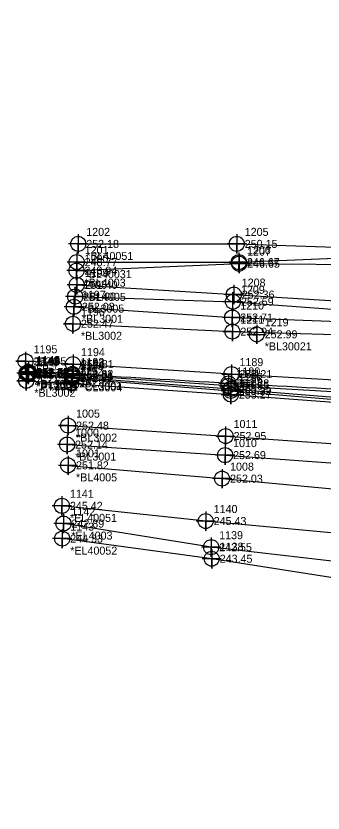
# Model space of a CAD drawing. Extents: x 2130962 to 2131465, y 643052 to 644206.
# Drawn here: x 2130981.3 to 2131077.2, y 643057.4 to 643306.2 of the extents above; entities that cross this region are included whole.
import ezdxf

# ---------------------------------------------------------------- set-up
doc = ezdxf.new("R2010")
doc.units = 0
for name, color, linetype in [('Exist DTM Breakline', 7, 'Continuous'), ('Exist DTM Breakline Cogo Comment', 7, 'Continuous'), ('Exist DTM Breakline Cogo Elevation', 7, 'Continuous'), ('Exist DTM Breakline Cogo Number', 7, 'Continuous'), ('Exist DTM Breakline Cogo Point CELL', 7, 'Continuous'), ('Exist DTM Drainline', 7, 'Continuous'), ('Exist DTM Drainline Cogo Comment', 7, 'Continuous'), ('Exist DTM Drainline Cogo Elevation', 7, 'Continuous'), ('Exist DTM Drainline Cogo Number', 7, 'Continuous'), ('Exist DTM Drainline Cogo Point CELL', 7, 'Continuous'), ('Exist Roads Curbs', 7, 'Continuous'), ('Exist Roads Curbs Cogo Comment', 7, 'Continuous'), ('Exist Roads Curbs Cogo Elevation', 7, 'Continuous'), ('Exist Roads Curbs Cogo Number', 7, 'Continuous'), ('Exist Roads Curbs Cogo Point CELL', 7, 'Continuous'), ('Exist Roads EOP', 7, 'Continuous'), ('Exist Roads EOP Cogo Comment', 7, 'Continuous'), ('Exist Roads EOP Cogo Elevation', 7, 'Continuous'), ('Exist Roads EOP Cogo Number', 7, 'Continuous'), ('Exist Roads EOP Cogo Point CELL', 7, 'Continuous'), ('Exist Roads EOT', 7, 'Continuous'), ('Exist Roads EOT Cogo Comment', 7, 'Continuous'), ('Exist Roads EOT Cogo Elevation', 7, 'Continuous'), ('Exist Roads EOT Cogo Number', 7, 'Continuous'), ('Exist Roads EOT Cogo Point CELL', 7, 'Continuous'), ('Exist Roads Soil', 7, 'Continuous'), ('Exist Roads Soil Cogo Comment', 7, 'Continuous'), ('Exist Roads Soil Cogo Elevation', 7, 'Continuous'), ('Exist Roads Soil Cogo Number', 7, 'Continuous'), ('Exist Roads Soil Cogo Point CELL', 7, 'Continuous')]:
    doc.layers.add(name, color=color, linetype=linetype)

msp = doc.modelspace()

# ---------------------------------------------------------------- linework, layer by layer
at = {"layer": 'Exist DTM Breakline'}
for points in [[(2131000.7408, 643235.0731), (2131050.2503, 643235.0771), (2131099.3971, 643233.3967), (2131102.4734, 643233.467), (2131117.9784, 643240.6457), (2131141.4902, 643260.2289), (2131148.9668, 643267.309), (2131161.3925, 643274.3195), (2131169.1458, 643283.2692), (2131172.0772, 643292.493), (2131174.434, 643316.7319), (2131174.0607, 643347.0813), (2131174.2633, 643367.3367), (2131180.4607, 643413.966), (2131183.0424, 643464.7744), (2131179.7562, 643510.5479), (2131157.5016, 643561.2065), (2131139.0887, 643604.6918), (2131124.996, 643650.6897)], [(2131000.2707, 643222.2884), (2131049.3172, 643219.2511), (2131099.5024, 643216.1866), (2131123.0232, 643217.8518), (2131146.7721, 643223.5416), (2131166.8509, 643229.4959), (2131199.4918, 643255.6512), (2131208.4065, 643272.9132), (2131217.3052, 643317.6851), (2131214.0619, 643367.4973), (2131211.0353, 643416.1836)], [(2130997.5489, 643165.941), (2131045.6664, 643161.7962), (2131094.7686, 643157.2786), (2131146.0902, 643153.1147), (2131194.5413, 643146.0346), (2131212.7846, 643137.5737), (2131227.5943, 643121.2545), (2131235.8712, 643098.3644), (2131243.3589, 643075.7514)], [(2131203.7387, 643060.6768), (2131200.323, 643080.6622), (2131194.2334, 643094.4284), (2131190.0903, 643104.0511), (2131182.9576, 643105.8495), (2131138.023, 643121.5465), (2131094.1742, 643143.5026), (2131040.5455, 643148.5531), (2130995.6405, 643153.3049)], [(2131190.282, 643057.3997), (2131185.0957, 643076.1853), (2131183.224, 643089.154), (2131178.6092, 643094.5527), (2131136.9713, 643111.7747), (2131091.5821, 643129.064), (2131042.4244, 643136.794), (2130995.734, 643143.071)]]:
    msp.add_lwpolyline(points, dxfattribs=at)
at = {"layer": 'Exist DTM Breakline Cogo Point CELL'}
for points in [[(2131000.7408, 643238.0731), (2131000.7408, 643232.0731), (2131000.7408, 643235.0731), (2131003.7408, 643235.0731), (2130997.7408, 643235.0731)], [(2131050.2503, 643238.0771), (2131050.2503, 643232.0771), (2131050.2503, 643235.0771), (2131053.2503, 643235.0771), (2131047.2503, 643235.0771)], [(2131000.2707, 643225.2884), (2131000.2707, 643219.2884), (2131000.2707, 643222.2884), (2131003.2707, 643222.2884), (2130997.2707, 643222.2884)], [(2131049.3172, 643222.2511), (2131049.3172, 643216.2511), (2131049.3172, 643219.2511), (2131052.3172, 643219.2511), (2131046.3172, 643219.2511)], [(2130997.5489, 643168.941), (2130997.5489, 643162.941), (2130997.5489, 643165.941), (2131000.5489, 643165.941), (2130994.5489, 643165.941)], [(2131045.6664, 643164.7962), (2131045.6664, 643158.7962), (2131045.6664, 643161.7962), (2131048.6664, 643161.7962), (2131042.6664, 643161.7962)], [(2130995.6405, 643156.3049), (2130995.6405, 643150.3049), (2130995.6405, 643153.3049), (2130998.6405, 643153.3049), (2130992.6405, 643153.3049)], [(2131040.5455, 643151.5531), (2131040.5455, 643145.5531), (2131040.5455, 643148.5531), (2131043.5455, 643148.5531), (2131037.5455, 643148.5531)], [(2130995.734, 643146.071), (2130995.734, 643140.071), (2130995.734, 643143.071), (2130998.734, 643143.071), (2130992.734, 643143.071)], [(2131042.4244, 643139.794), (2131042.4244, 643133.794), (2131042.4244, 643136.794), (2131045.4244, 643136.794), (2131039.4244, 643136.794)]]:
    msp.add_lwpolyline(points, dxfattribs=at)
for centre in [(2131000.7408, 643235.0731), (2131050.2503, 643235.0771), (2131000.2707, 643222.2884), (2131049.3172, 643219.2511), (2130997.5489, 643165.941), (2131045.6664, 643161.7962), (2130995.6405, 643153.3049), (2131040.5455, 643148.5531), (2130995.734, 643143.071), (2131042.4244, 643136.794)]:
    msp.add_circle(centre, 2.344, dxfattribs=at)
at = {"layer": 'Exist DTM Drainline'}
for points in [[(2131000.2029, 643226.7228), (2131050.9884, 643228.9032), (2131099.0297, 643228.5605), (2131120.2968, 643239.3591), (2131144.9156, 643253.3469), (2131146.4739, 643252.3674), (2131154.3188, 643256.8046), (2131168.9618, 643265.5132), (2131176.6257, 643272.964), (2131179.8144, 643285.303), (2131183.3842, 643315.022), (2131190.1471, 643365.8731), (2131190.1489, 643413.686), (2131192.3886, 643466.4632), (2131188.8083, 643512.615), (2131184.0059, 643563.7066), (2131175.3, 643610.7482), (2131168.3784, 643658.7431), (2131156.7476, 643707.4708), (2131144.9036, 643754.0458), (2131132.9438, 643802.544), (2131118.0831, 643847.9475), (2131104.0084, 643896.8663), (2131096.3866, 643919.4077)], [(2131000.2521, 643229.3945), (2131050.9247, 643229.3918), (2131098.5522, 643231.3283), (2131118.2949, 643238.5741)], [(2131198.1997, 643059.006), (2131193.6429, 643078.1873), (2131189.8038, 643092.9639), (2131187.1852, 643097.4954), (2131182.6436, 643103.2956), (2131182.1533, 643099.9067), (2131137.3651, 643115.851), (2131092.5788, 643134.5516), (2131042.2635, 643140.3935), (2130996.1192, 643147.7639)]]:
    msp.add_lwpolyline(points, dxfattribs=at)
at = {"layer": 'Exist DTM Drainline Cogo Point CELL'}
for points in [[(2131000.2521, 643232.3945), (2131000.2521, 643226.3945), (2131000.2521, 643229.3945), (2131003.2521, 643229.3945), (2130997.2521, 643229.3945)], [(2131050.9247, 643232.3918), (2131050.9247, 643226.3918), (2131050.9247, 643229.3918), (2131053.9247, 643229.3918), (2131047.9247, 643229.3918)], [(2131050.9884, 643231.9032), (2131050.9884, 643225.9032), (2131050.9884, 643228.9032), (2131053.9884, 643228.9032), (2131047.9884, 643228.9032)], [(2131000.2029, 643229.7228), (2131000.2029, 643223.7228), (2131000.2029, 643226.7228), (2131003.2029, 643226.7228), (2130997.2029, 643226.7228)], [(2130996.1192, 643150.7639), (2130996.1192, 643144.7639), (2130996.1192, 643147.7639), (2130999.1192, 643147.7639), (2130993.1192, 643147.7639)], [(2131042.2635, 643143.3935), (2131042.2635, 643137.3935), (2131042.2635, 643140.3935), (2131045.2635, 643140.3935), (2131039.2635, 643140.3935)]]:
    msp.add_lwpolyline(points, dxfattribs=at)
for centre in [(2131000.2521, 643229.3945), (2131050.9247, 643229.3918), (2131050.9884, 643228.9032), (2131000.2029, 643226.7228), (2130996.1192, 643147.7639), (2131042.2635, 643140.3935)]:
    msp.add_circle(centre, 2.344, dxfattribs=at)
at = {"layer": 'Exist Roads Curbs'}
for points in [[(2131198.0624, 643180.7236), (2131148.4553, 643184.4513), (2131096.3634, 643187.9153), (2131047.6348, 643190.8052), (2130998.9825, 643194.049), (2130985.1601, 643194.9243)], [(2130985.2008, 643194.5895), (2130998.8721, 643193.5705), (2131048.4066, 643189.8131), (2131096.2876, 643185.9927), (2131148.0156, 643182.2174), (2131198.038, 643178.5389), (2131226.4879, 643176.4123)]]:
    msp.add_lwpolyline(points, dxfattribs=at)
at = {"layer": 'Exist Roads Curbs Cogo Point CELL'}
for points in [[(2130984.9827, 643197.7718), (2130984.9827, 643191.7718), (2130984.9827, 643194.7718), (2130982.2527, 643194.7718), (2130987.9827, 643194.7718)], [(2130985.1601, 643197.9243), (2130985.1601, 643191.9243), (2130985.1601, 643194.9243), (2130982.4301, 643194.9243), (2130988.1601, 643194.9243)], [(2130985.2008, 643197.5895), (2130985.2008, 643191.5895), (2130985.2008, 643194.5895), (2130982.4708, 643194.5895), (2130988.2008, 643194.5895)], [(2130998.8721, 643196.5705), (2130998.8721, 643190.5705), (2130998.8721, 643193.5705), (2130996.1421, 643193.5705), (2131001.8721, 643193.5705)], [(2130998.9825, 643197.049), (2130998.9825, 643191.049), (2130998.9825, 643194.049), (2130996.2525, 643194.049), (2131001.9825, 643194.049)], [(2131047.6348, 643193.8052), (2131047.6348, 643187.8052), (2131047.6348, 643190.8052), (2131044.9048, 643190.8052), (2131050.6348, 643190.8052)], [(2131048.4066, 643192.8131), (2131048.4066, 643186.8131), (2131048.4066, 643189.8131), (2131045.6766, 643189.8131), (2131051.4066, 643189.8131)]]:
    msp.add_lwpolyline(points, dxfattribs=at)
for centre in [(2130984.9827, 643194.7718), (2130985.1601, 643194.9243), (2130985.2008, 643194.5895), (2130998.9825, 643194.049), (2130998.8721, 643193.5705), (2131047.6348, 643190.8052), (2131048.4066, 643189.8131)]:
    msp.add_circle(centre, 2.344, dxfattribs=at)
at = {"layer": 'Exist Roads EOP'}
msp.add_line((2130998.9471, 643194.464), (2130985.1949, 643195.1145), dxfattribs=at)
for points in [[(2130999.387, 643215.4489), (2131048.8311, 643212.0849), (2131098.77, 643210.1813), (2131123.476, 643210.5181)], [(2130985.0681, 643194.3028), (2130998.8642, 643193.2032), (2131048.3641, 643189.1686), (2131096.0386, 643185.2243), (2131148.0312, 643181.1875), (2131197.8595, 643177.8797), (2131226.6095, 643175.7594)], [(2130997.2568, 643172.4279), (2131046.6093, 643169.1365), (2131095.2834, 643165.6174), (2131146.4463, 643162.1202), (2131188.4433, 643158.2198), (2131196.4033, 643155.8931)]]:
    msp.add_lwpolyline(points, dxfattribs=at)
msp.add_spline([(2131226.9097, 643179.1731), (2131198.0663, 643181.4699), (2131148.43, 643185.1482), (2131096.4958, 643188.7823), (2131047.6681, 643191.5278), (2130998.9471, 643194.464)], degree=3, dxfattribs=at)
at = {"layer": 'Exist Roads EOP Cogo Point CELL'}
for points in [[(2130999.387, 643218.4489), (2130999.387, 643212.4489), (2130999.387, 643215.4489), (2131002.387, 643215.4489), (2130996.387, 643215.4489)], [(2131048.8311, 643215.0849), (2131048.8311, 643209.0849), (2131048.8311, 643212.0849), (2131051.8311, 643212.0849), (2131045.8311, 643212.0849)], [(2130984.6006, 643197.6874), (2130984.6006, 643191.6874), (2130984.6006, 643194.6874), (2130987.6006, 643194.6874), (2130981.6006, 643194.6874)], [(2130985.0681, 643197.3028), (2130985.0681, 643191.3028), (2130985.0681, 643194.3028), (2130988.0681, 643194.3028), (2130982.0681, 643194.3028)], [(2130985.1949, 643198.1145), (2130985.1949, 643192.1145), (2130985.1949, 643195.1145), (2130988.1949, 643195.1145), (2130982.1949, 643195.1145)], [(2130998.8642, 643196.2032), (2130998.8642, 643190.2032), (2130998.8642, 643193.2032), (2131001.8642, 643193.2032), (2130995.8642, 643193.2032)], [(2130998.9471, 643197.464), (2130998.9471, 643191.464), (2130998.9471, 643194.464), (2131001.9471, 643194.464), (2130995.9471, 643194.464)], [(2131047.6681, 643194.5278), (2131047.6681, 643188.5278), (2131047.6681, 643191.5278), (2131050.6681, 643191.5278), (2131044.6681, 643191.5278)], [(2131048.3641, 643192.1686), (2131048.3641, 643186.1686), (2131048.3641, 643189.1686), (2131051.3641, 643189.1686), (2131045.3641, 643189.1686)], [(2130997.2568, 643175.4279), (2130997.2568, 643169.4279), (2130997.2568, 643172.4279), (2131000.2568, 643172.4279), (2130994.2568, 643172.4279)], [(2131046.6093, 643172.1365), (2131046.6093, 643166.1365), (2131046.6093, 643169.1365), (2131049.6093, 643169.1365), (2131043.6093, 643169.1365)]]:
    msp.add_lwpolyline(points, dxfattribs=at)
for centre in [(2130999.387, 643215.4489), (2131048.8311, 643212.0849), (2130984.6006, 643194.6874), (2130985.0681, 643194.3028), (2130985.1949, 643195.1145), (2130998.9471, 643194.464), (2130998.8642, 643193.2032), (2131047.6681, 643191.5278), (2131048.3641, 643189.1686), (2130997.2568, 643172.4279), (2131046.6093, 643169.1365)]:
    msp.add_circle(centre, 2.344, dxfattribs=at)
at = {"layer": 'Exist Roads EOT'}
for points in [[(2130999.0837, 643210.149), (2131048.883, 643207.6861), (2131098.6093, 643206.3137), (2131123.8135, 643207.212)], [(2130984.5181, 643192.3513), (2130998.5672, 643191.5434), (2131048.4259, 643188.0549), (2131095.8768, 643184.5731), (2131148.0696, 643180.6818), (2131197.8229, 643176.9862), (2131227.4987, 643174.8043), (2131230.1348, 643175.616), (2131231.2992, 643177.7905), (2131229.0582, 643182.3901), (2131224.2697, 643184.0454), (2131198.1991, 643185.755), (2131149.0546, 643188.5149), (2131096.726, 643191.5809), (2131048.6064, 643194.4262), (2130999.1051, 643197.5379), (2130984.2748, 643198.4247)], [(2130997.5703, 643178.3518), (2131046.7671, 643175.0968), (2131095.9912, 643171.5914), (2131146.7075, 643168.0129), (2131169.9901, 643166.2046), (2131196.9631, 643160.4097)]]:
    msp.add_lwpolyline(points, dxfattribs=at)
msp.add_spline([(2131166.718, 643215.2083), (2131172.3866, 643217.1804), (2131211.4056, 643247.1499), (2131223.758, 643268.7314), (2131228.3848, 643317.935), (2131225.533, 643367.8628), (2131222.2486, 643417.1873), (2131217.9619, 643466.6275), (2131212.8794, 643516.2377), (2131206.5633, 643565.5764), (2131198.9021, 643614.6757), (2131189.6851, 643663.4055), (2131179.3985, 643712.1311), (2131168.3085, 643760.7185), (2131155.755, 643808.9129), (2131141.6748, 643856.5528), (2131126.5354, 643904.2758), (2131110.3559, 643951.0191), (2131092.4533, 643998.1348), (2131073.722, 644043.631), (2131053.1654, 644089.359), (2131032.0052, 644134.0908), (2131009.0644, 644179.3802)], degree=3, dxfattribs=at)
at = {"layer": 'Exist Roads EOT Cogo Point CELL'}
for points in [[(2130999.0837, 643213.149), (2130999.0837, 643207.149), (2130999.0837, 643210.149), (2130996.0837, 643210.149), (2131002.0837, 643210.149)], [(2131048.883, 643210.6861), (2131048.883, 643204.6861), (2131048.883, 643207.6861), (2131045.883, 643207.6861), (2131051.883, 643207.6861)], [(2131056.4913, 643209.8397), (2131056.4913, 643203.8397), (2131056.4913, 643206.8397), (2131053.4913, 643206.8397), (2131059.4913, 643206.8397)], [(2130984.2748, 643201.4247), (2130984.2748, 643195.4247), (2130984.2748, 643198.4247), (2130981.2748, 643198.4247), (2130987.2748, 643198.4247)], [(2130999.1051, 643200.5379), (2130999.1051, 643194.5379), (2130999.1051, 643197.5379), (2130996.1051, 643197.5379), (2131002.1051, 643197.5379)], [(2131048.6064, 643197.4262), (2131048.6064, 643191.4262), (2131048.6064, 643194.4262), (2131045.6064, 643194.4262), (2131051.6064, 643194.4262)], [(2130984.5181, 643195.3513), (2130984.5181, 643189.3513), (2130984.5181, 643192.3513), (2130981.5181, 643192.3513), (2130987.5181, 643192.3513)], [(2130998.5672, 643194.5434), (2130998.5672, 643188.5434), (2130998.5672, 643191.5434), (2130995.5672, 643191.5434), (2131001.5672, 643191.5434)], [(2131048.4259, 643191.0549), (2131048.4259, 643185.0549), (2131048.4259, 643188.0549), (2131045.4259, 643188.0549), (2131051.4259, 643188.0549)], [(2130997.5703, 643181.3518), (2130997.5703, 643175.3518), (2130997.5703, 643178.3518), (2130994.5703, 643178.3518), (2131000.5703, 643178.3518)], [(2131046.7671, 643178.0968), (2131046.7671, 643172.0968), (2131046.7671, 643175.0968), (2131043.7671, 643175.0968), (2131049.7671, 643175.0968)]]:
    msp.add_lwpolyline(points, dxfattribs=at)
for centre in [(2130999.0837, 643210.149), (2131048.883, 643207.6861), (2131056.4913, 643206.8397), (2130984.2748, 643198.4247), (2130999.1051, 643197.5379), (2131048.6064, 643194.4262), (2130984.5181, 643192.3513), (2130998.5672, 643191.5434), (2131048.4259, 643188.0549), (2130997.5703, 643178.3518), (2131046.7671, 643175.0968)]:
    msp.add_circle(centre, 2.344, dxfattribs=at)
at = {"layer": 'Exist Roads Soil'}
msp.add_lwpolyline([(2130999.7918, 643218.6269), (2131049.0553, 643217.0164), (2131083.0054, 643214.4454), (2131098.7667, 643210.2105)], dxfattribs=at)
at = {"layer": 'Exist Roads Soil Cogo Point CELL'}
for points in [[(2130999.7918, 643215.6269), (2130999.7918, 643221.6269), (2130999.7918, 643218.6269), (2131002.7918, 643218.6269), (2130996.7918, 643218.6269)], [(2131049.0553, 643214.0164), (2131049.0553, 643220.0164), (2131049.0553, 643217.0164), (2131052.0553, 643217.0164), (2131046.0553, 643217.0164)]]:
    msp.add_lwpolyline(points, dxfattribs=at)
for centre in [(2130999.7918, 643218.6269), (2131049.0553, 643217.0164)]:
    msp.add_circle(centre, 2.344, dxfattribs=at)

# ---------------------------------------------------------------- texts
at = {"layer": 'Exist DTM Breakline Cogo Comment'}
for s, p in [('*BL40051', (2131003.2408, 643230.0731)), ('*BL4005', (2131002.7707, 643217.2884)), ('*BL4005', (2131000.0489, 643160.941)), ('*EL40051', (2130998.1405, 643148.3049)), ('*EL40052', (2130998.234, 643138.071))]:
    msp.add_text(s, height=2.5, dxfattribs=at).set_placement(p)
at = {"layer": 'Exist DTM Breakline Cogo Elevation'}
for s, p in [('252.18', (2131003.2408, 643233.8231)), ('250.15', (2131052.7503, 643233.8271)), ('251.40', (2131002.7707, 643221.0384)), ('252.36', (2131051.8172, 643218.0011)), ('251.82', (2131000.0489, 643164.691)), ('252.03', (2131048.1664, 643160.5462)), ('245.42', (2130998.1405, 643152.0549)), ('245.43', (2131043.0455, 643147.3031)), ('244.33', (2130998.234, 643141.821)), ('243.45', (2131044.9244, 643135.544))]:
    msp.add_text(s, height=2.5, dxfattribs=at).set_placement(p)
at = {"layer": 'Exist DTM Breakline Cogo Number'}
for s, p in [('1202', (2131003.2408, 643237.5731)), ('1205', (2131052.7503, 643237.5771)), ('1199', (2131002.7707, 643224.7884)), ('1208', (2131051.8172, 643221.7511)), ('1001', (2131000.0489, 643168.441)), ('1008', (2131048.1664, 643164.2962)), ('1141', (2130998.1405, 643155.8049)), ('1140', (2131043.0455, 643151.0531)), ('1143', (2130998.234, 643145.571)), ('1138', (2131044.9244, 643139.294))]:
    msp.add_text(s, height=2.5, dxfattribs=at).set_placement(p)
at = {"layer": 'Exist DTM Drainline Cogo Comment'}
for s, p in [('*BL40031', (2131002.7521, 643224.3945)), ('*BL4003', (2131002.7029, 643221.7228)), ('*EL4003', (2130998.6192, 643142.7639))]:
    msp.add_text(s, height=2.5, dxfattribs=at).set_placement(p)
at = {"layer": 'Exist DTM Drainline Cogo Elevation'}
for s, p in [('248.77', (2131002.7521, 643228.1445)), ('246.67', (2131053.4247, 643228.1418)), ('246.65', (2131053.4884, 643227.6532)), ('248.94', (2131002.7029, 643225.4728)), ('242.89', (2130998.6192, 643146.5139)), ('242.55', (2131044.7635, 643139.1435))]:
    msp.add_text(s, height=2.5, dxfattribs=at).set_placement(p)
at = {"layer": 'Exist DTM Drainline Cogo Number'}
for s, p in [('1201', (2131002.7521, 643231.8945)), ('1206', (2131053.4247, 643231.8918)), ('1207', (2131053.4884, 643231.4032)), ('1200', (2131002.7029, 643229.2228)), ('1142', (2130998.6192, 643150.2639)), ('1139', (2131044.7635, 643142.8935))]:
    msp.add_text(s, height=2.5, dxfattribs=at).set_placement(p)
at = {"layer": 'Exist Roads Curbs Cogo Comment'}
for s, p in [('*BL3004', (2130987.6601, 643189.9243)), ('*PT3004', (2130987.7008, 643189.5895)), ('*CL3004', (2131001.4825, 643189.049))]:
    msp.add_text(s, height=2.5, dxfattribs=at).set_placement(p)
at = {"layer": 'Exist Roads Curbs Cogo Elevation'}
for s, p in [('252.78', (2130987.4827, 643193.5218)), ('252.81', (2130987.6601, 643193.6743)), ('252.80', (2130987.7008, 643193.3395)), ('253.00', (2131001.3721, 643192.3205)), ('253.01', (2131001.4825, 643192.799)), ('253.55', (2131050.1348, 643189.5552)), ('253.55', (2131050.9066, 643188.5631))]:
    msp.add_text(s, height=2.5, dxfattribs=at).set_placement(p)
at = {"layer": 'Exist Roads Curbs Cogo Number'}
for s, p in [('1149', (2130987.4827, 643197.2718)), ('1148', (2130987.6601, 643197.4243)), ('1150', (2130987.7008, 643197.0895)), ('1154', (2131001.3721, 643196.0705)), ('1192', (2131001.4825, 643196.549)), ('1191', (2131050.1348, 643193.3052)), ('1157', (2131050.9066, 643192.3131))]:
    msp.add_text(s, height=2.5, dxfattribs=at).set_placement(p)
at = {"layer": 'Exist Roads EOP Cogo Comment'}
for s, p in [('*BL3001', (2131001.887, 643210.4489)), ('*PT3001', (2130987.5681, 643189.3028)), ('*BL3001', (2130987.6949, 643190.1145)), ('*CL3001', (2131001.4471, 643189.464)), ('*BL3001', (2130999.7568, 643167.4279))]:
    msp.add_text(s, height=2.5, dxfattribs=at).set_placement(p)
at = {"layer": 'Exist Roads EOP Cogo Elevation'}
for s, p in [('252.08', (2131001.887, 643214.1989)), ('252.71', (2131051.3311, 643210.8349)), ('252.75', (2130987.6949, 643193.8645)), ('252.70', (2130987.1006, 643193.4374)), ('252.67', (2130987.5681, 643193.0528)), ('252.82', (2131001.3642, 643191.9532)), ('252.82', (2131001.4471, 643193.214)), ('253.28', (2131050.1681, 643190.2778)), ('253.32', (2131050.8641, 643187.9186)), ('252.14', (2130999.7568, 643171.1779)), ('252.69', (2131049.1093, 643167.8865))]:
    msp.add_text(s, height=2.5, dxfattribs=at).set_placement(p)
at = {"layer": 'Exist Roads EOP Cogo Number'}
for s, p in [('1197', (2131001.887, 643217.9489)), ('1210', (2131051.3311, 643214.5849)), ('1146', (2130987.1006, 643197.1874)), ('1147', (2130987.5681, 643196.8028)), ('1145', (2130987.6949, 643197.6145)), ('1193', (2131001.4471, 643196.964)), ('1153', (2131001.3642, 643195.7032)), ('1190', (2131050.1681, 643194.0278)), ('1156', (2131050.8641, 643191.6686)), ('1000', (2130999.7568, 643174.9279)), ('1010', (2131049.1093, 643171.6365))]:
    msp.add_text(s, height=2.5, dxfattribs=at).set_placement(p)
at = {"layer": 'Exist Roads EOT Cogo Comment'}
for s, p in [('*BL3002', (2131001.5837, 643205.149)), ('*BL30021', (2131058.9913, 643201.8397)), ('*EL3002', (2130986.7748, 643193.4247)), ('*BL3002', (2130987.0181, 643187.3513)), ('*BL3002', (2131000.0703, 643173.3518))]:
    msp.add_text(s, height=2.5, dxfattribs=at).set_placement(p)
at = {"layer": 'Exist Roads EOT Cogo Elevation'}
for s, p in [('252.47', (2131001.5837, 643208.899)), ('252.94', (2131051.383, 643206.4361)), ('252.99', (2131058.9913, 643205.5897)), ('252.65', (2130986.7748, 643197.1747)), ('252.81', (2131001.6051, 643196.2879)), ('252.63', (2130987.0181, 643191.1013)), ('253.21', (2131051.1064, 643193.1762)), ('252.77', (2131001.0672, 643190.2934)), ('253.27', (2131050.9259, 643186.8049)), ('252.48', (2131000.0703, 643177.1018)), ('252.95', (2131049.2671, 643173.8468))]:
    msp.add_text(s, height=2.5, dxfattribs=at).set_placement(p)
at = {"layer": 'Exist Roads EOT Cogo Number'}
for s, p in [('1196', (2131001.5837, 643212.649)), ('1211', (2131051.383, 643210.1861)), ('1219', (2131058.9913, 643209.3397)), ('1195', (2130986.7748, 643200.9247)), ('1194', (2131001.6051, 643200.0379)), ('1189', (2131051.1064, 643196.9262)), ('1151', (2130987.0181, 643194.8513)), ('1152', (2131001.0672, 643194.0434)), ('1158', (2131050.9259, 643190.5549)), ('1005', (2131000.0703, 643180.8518)), ('1011', (2131049.2671, 643177.5968))]:
    msp.add_text(s, height=2.5, dxfattribs=at).set_placement(p)
at = {"layer": 'Exist Roads Soil Cogo Comment'}
msp.add_text('*BL3005', height=2.5, dxfattribs=at).set_placement((2131002.2918, 643213.6269))
at = {"layer": 'Exist Roads Soil Cogo Elevation'}
for s, p in [('251.90', (2131002.2918, 643217.3769)), ('252.59', (2131051.5553, 643215.7664))]:
    msp.add_text(s, height=2.5, dxfattribs=at).set_placement(p)
at = {"layer": 'Exist Roads Soil Cogo Number'}
for s, p in [('1198', (2131002.2918, 643221.1269)), ('1209', (2131051.5553, 643219.5164))]:
    msp.add_text(s, height=2.5, dxfattribs=at).set_placement(p)

doc.saveas('drawing.dxf')
